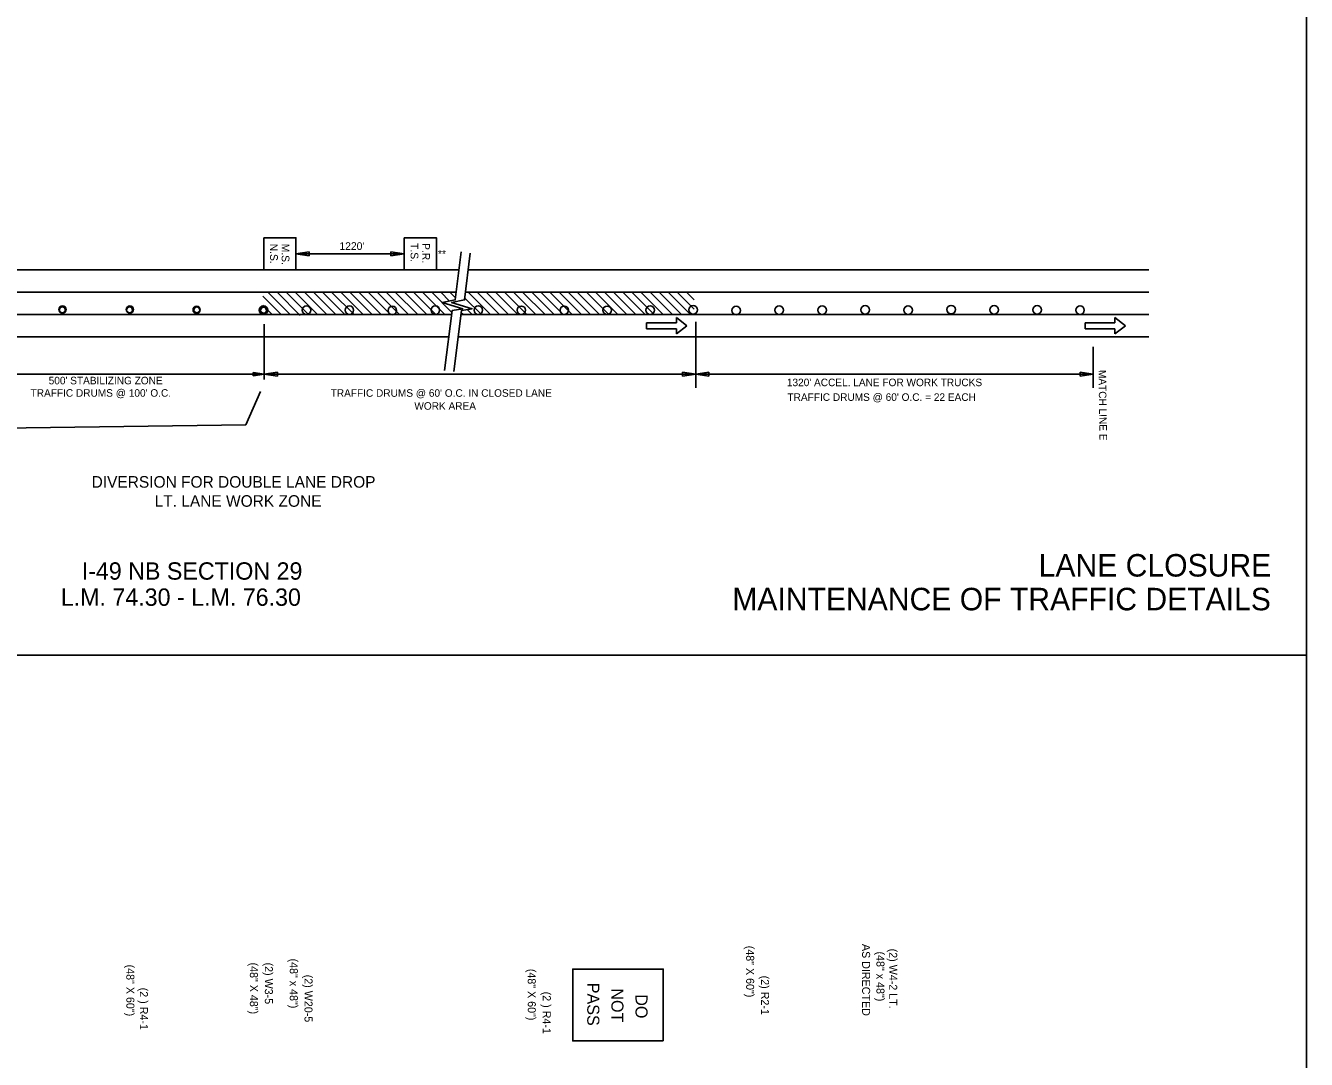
# Model space of a CAD drawing. Extents: x -100 to 745, y -1581 to -107.
# Drawn here: x 245.8 to 345.4, y -732 to -651.6 of the extents above; entities that cross this region are included whole.
import ezdxf

# ---------------------------------------------------------------- set-up
doc = ezdxf.new("R2010")
doc.units = 0
for name, color, linetype in [('Default', 7, 'Continuous'), ('R_Contour Annot', 7, 'Continuous'), ('R_Draft', 7, 'Continuous'), ('R_MOT', 7, 'Continuous'), ('R_ROW', 7, 'Continuous')]:
    doc.layers.add(name, color=color, linetype=linetype)

msp = doc.modelspace()

# ---------------------------------------------------------------- linework, layer by layer
at = {"layer": 'Default'}
for p, q in [((266.853, -669.361), (267.883, -669.206)), ((275.274, -669.361), (266.853, -669.361)), ((267.883, -669.515), (266.853, -669.361)), ((267.883, -669.206), (267.883, -669.515)), ((274.243, -669.515), (274.243, -669.206)), ((274.243, -669.206), (275.274, -669.361)), ((275.274, -669.361), (274.243, -669.515)), ((220.475, -670.611), (279.525, -670.611)), ((280.254, -670.611), (333.152, -670.611)), ((220.692, -672.349), (279.316, -672.349)), ((264.277, -672.648), (265.717, -674.088)), ((264.685, -672.349), (266.424, -674.088)), ((265.393, -672.349), (267.186, -674.143)), ((266.1, -672.349), (267.838, -674.088)), ((266.807, -672.349), (268.545, -674.088)), ((267.514, -672.349), (269.252, -674.088)), ((268.221, -672.349), (269.959, -674.088)), ((268.928, -672.349), (270.666, -674.088)), ((269.635, -672.349), (271.374, -674.088)), ((270.342, -672.349), (272.081, -674.088)), ((271.049, -672.349), (272.788, -674.088)), ((271.757, -672.349), (273.495, -674.088)), ((272.464, -672.349), (274.202, -674.088)), ((273.171, -672.349), (274.909, -674.088)), ((273.878, -672.349), (275.616, -674.088)), ((274.585, -672.349), (276.323, -674.088)), ((275.292, -672.349), (277.03, -674.088)), ((275.999, -672.349), (277.737, -674.088)), ((276.706, -672.349), (278.445, -674.088)), ((277.413, -672.349), (278.983, -673.919)), ((278.121, -672.349), (278.802, -673.03)), ((278.827, -672.349), (279.263, -672.785)), ((279.99, -672.804), (281.273, -674.088)), ((280.044, -672.349), (333.152, -672.349)), ((280.242, -672.349), (281.98, -674.088)), ((280.949, -672.349), (282.687, -674.088)), ((281.656, -672.349), (283.394, -674.088)), ((282.363, -672.349), (284.101, -674.088)), ((283.07, -672.349), (284.809, -674.088)), ((283.777, -672.349), (285.516, -674.088)), ((284.484, -672.349), (286.223, -674.088)), ((285.192, -672.349), (286.93, -674.088)), ((285.899, -672.349), (287.637, -674.088)), ((286.606, -672.349), (288.344, -674.088)), ((287.313, -672.349), (289.051, -674.088)), ((288.02, -672.349), (289.758, -674.088)), ((288.727, -672.349), (290.465, -674.088)), ((289.434, -672.349), (291.172, -674.088)), ((290.141, -672.349), (291.88, -674.088)), ((290.848, -672.349), (292.587, -674.088)), ((291.556, -672.349), (293.294, -674.088)), ((292.263, -672.349), (294.001, -674.088)), ((292.97, -672.349), (294.708, -674.088)), ((293.677, -672.349), (295.415, -674.088)), ((294.384, -672.349), (296.122, -674.088)), ((295.091, -672.349), (296.829, -674.088)), ((295.798, -672.349), (297.536, -674.088)), ((296.505, -672.349), (297.812, -673.656)), ((297.212, -672.349), (297.812, -672.949)), ((264.277, -673.355), (265.01, -674.088)), ((279.709, -673.938), (279.859, -674.088)), ((280.172, -673.694), (280.566, -674.088)), ((221.048, -674.088), (278.962, -674.088)), ((264.398, -679.129), (264.398, -674.824)), ((279.69, -674.088), (333.152, -674.088)), ((296.438, -674.72), (294.113, -674.72)), ((294.113, -675.194), (294.113, -674.72)), ((296.438, -674.72), (296.438, -674.324)), ((297.259, -674.957), (296.438, -674.324)), ((296.438, -675.589), (297.259, -674.957)), ((297.933, -679.793), (297.933, -674.648)), ((330.524, -674.72), (328.198, -674.72)), ((328.198, -675.194), (328.198, -674.72)), ((330.524, -674.72), (330.524, -674.324)), ((331.344, -674.957), (330.524, -674.324)), ((330.524, -675.589), (331.344, -674.957)), ((220.528, -675.826), (278.745, -675.826)), ((279.473, -675.826), (333.152, -675.826)), ((296.438, -675.194), (294.113, -675.194)), ((296.438, -675.589), (296.438, -675.194)), ((330.524, -675.194), (328.198, -675.194)), ((330.524, -675.589), (330.524, -675.194)), ((328.843, -679.793), (328.843, -676.602)), ((264.398, -678.715), (238.32, -678.715)), ((264.398, -678.715), (263.528, -678.584)), ((263.528, -678.584), (263.528, -678.845)), ((263.528, -678.845), (264.398, -678.715)), ((265.428, -678.56), (264.398, -678.715)), ((297.933, -678.715), (264.398, -678.715)), ((264.398, -678.715), (265.428, -678.87)), ((265.428, -678.87), (265.428, -678.56)), ((297.933, -678.715), (296.902, -678.56)), ((296.902, -678.56), (296.902, -678.869)), ((296.902, -678.869), (297.933, -678.715)), ((298.963, -678.56), (297.933, -678.715)), ((328.843, -678.715), (297.933, -678.715)), ((297.933, -678.715), (298.963, -678.87)), ((298.963, -678.87), (298.963, -678.56)), ((328.843, -678.715), (327.813, -678.56)), ((327.813, -678.56), (327.813, -678.87)), ((327.813, -678.87), (328.843, -678.715))]:
    msp.add_line(p, q, dxfattribs=at)
for points in [[(264.353, -668.111), (266.853, -668.111), (266.853, -670.611), (264.353, -670.611)], [(275.274, -668.111), (277.774, -668.111), (277.774, -670.611), (275.274, -670.611)], [(295.412, -730.566), (288.372, -730.566), (288.372, -724.98), (295.412, -724.98)]]:
    msp.add_lwpolyline(points, close=True, dxfattribs=at)
for points in [[(278.42, -678.429), (279.001, -673.772), (279.827, -673.626), (278.224, -673.14), (279.244, -672.946), (279.694, -669.211)], [(279.137, -678.518), (279.73, -673.772), (280.555, -673.626), (278.953, -673.14), (279.973, -672.946), (280.412, -669.297)], [(193.606, -680.302), (195.581, -682.919), (237.407, -682.968), (238.213, -685.387), (238.285, -683.002), (262.954, -682.669), (264.095, -680.071)]]:
    msp.add_lwpolyline(points, dxfattribs=at)
for centre, radius in [((248.712, -673.688), 0.281), ((248.704, -673.718), 0.229), ((253.954, -673.688), 0.281), ((253.931, -673.718), 0.229), ((259.141, -673.715), 0.281), ((259.158, -673.718), 0.229), ((264.332, -673.745), 0.333), ((264.327, -673.741), 0.281), ((264.345, -673.744), 0.229), ((267.673, -673.745), 0.333), ((271.014, -673.746), 0.333), ((274.355, -673.766), 0.333), ((277.696, -673.745), 0.333), ((281.037, -673.734), 0.333), ((284.379, -673.75), 0.333), ((287.72, -673.75), 0.333), ((291.061, -673.75), 0.333), ((294.402, -673.735), 0.333), ((297.743, -673.722), 0.333), ((301.084, -673.77), 0.333), ((304.425, -673.738), 0.333), ((307.766, -673.738), 0.333), ((311.107, -673.722), 0.333), ((314.448, -673.736), 0.333), ((317.789, -673.7), 0.333), ((321.13, -673.722), 0.333), ((324.471, -673.719), 0.333), ((327.812, -673.735), 0.333)]:
    msp.add_circle(centre, radius, dxfattribs=at)
at = {"layer": 'R_Contour Annot'}
for points in [[(175.406, -590.582), (345.406, -590.582), (345.406, -700.582), (175.406, -700.582)], [(175.406, -700.582), (345.406, -700.582), (345.406, -810.582), (175.406, -810.582)]]:
    msp.add_lwpolyline(points, close=True, dxfattribs=at)
at = {"layer": 'R_Draft'}
for points in [[(175.406, -590.582), (175.406, -700.582), (345.406, -700.582), (345.406, -590.582)], [(175.406, -700.582), (175.406, -810.582), (345.406, -810.582), (345.406, -700.582)]]:
    msp.add_lwpolyline(points, close=True, dxfattribs=at)

# ---------------------------------------------------------------- texts
at = {"layer": 'Default'}
for s, height, rotation, p in [('N.S.', 0.6, 270, (264.853, -668.569)), ('M.S.', 0.6, 270, (265.753, -668.569)), ('T.S.', 0.6, 270, (275.774, -668.522)), ('P.R.', 0.6, 270, (276.674, -668.522)), ('MATCH LINE E', 0.5862, 270.80593, (329.249, -678.396)), ('(48" X 60")', 0.6222, 270, (301.857, -723.166)), ('AS DIRECTED ', 0.6222, 270, (310.87, -723.027)), ('(48" x 48")', 0.6222, 270, (311.988, -723.616)), ('(2) W4-2 LT.', 0.6222, 270, (312.975, -723.394)), ('(48" X 60")', 0.6222, 270, (253.679, -724.634)), ('(48" X 48")', 0.6222, 270, (263.28, -724.474)), ('(2) W3-5', 0.6222, 270, (264.443, -724.474)), ('(48" x 48")', 0.6222, 270, (266.385, -724.163)), ('(2) W20-5', 0.6222, 270, (267.527, -725.42)), ('(48" X 60")', 0.6222, 270, (284.882, -724.962)), ('(2) R2-1', 0.6222, 270, (303.015, -725.492)), ('(2 ) R4-1', 0.6222, 270, (254.731, -726.43)), ('PASS', 0.937, 270, (289.507, -726.045)), ('NOT', 0.9371, 270, (291.381, -726.481)), ('(2 ) R4-1', 0.6222, 270, (286.051, -726.739)), ('DO', 0.9371, 270, (293.255, -726.939))]:
    msp.add_text(s, height=height, rotation=rotation, dxfattribs=at).set_placement(p)
for s, height, p in [("1220'", 0.6, (270.241, -669.057)), ('**', 0.6, (277.897, -669.661)), ("500' STABILIZING ZONE", 0.5862, (247.639, -679.507)), ("TRAFFIC DRUMS @ 100' O.C.", 0.5862, (246.234, -680.471)), ("TRAFFIC DRUMS @ 60' O.C. IN CLOSED LANE", 0.5862, (269.561, -680.476)), ("1320' ACCEL. LANE FOR WORK TRUCKS", 0.5862, (305.022, -679.652)), ('WORK AREA', 0.5862, (276.065, -681.484)), ("TRAFFIC DRUMS @ 60' O.C. = 22 EACH", 0.5862, (305.07, -680.795)), ('I-49 NB SECTION 29', 1.35, (250.207, -694.699)), ('L.M. 74.30 - L.M. 76.30', 1.35, (248.58, -696.732))]:
    msp.add_text(s, height=height, dxfattribs=at).set_placement(p)
at = {"layer": 'R_MOT'}
for s, p in [('LANE CLOSURE', (324.596, -694.457)), ('MAINTENANCE OF TRAFFIC DETAILS', (300.779, -697.082))]:
    msp.add_text(s, height=1.75, dxfattribs=at).set_placement(p)
at = {"layer": 'R_ROW'}
for s, p in [('DIVERSION FOR DOUBLE LANE DROP', (250.976, -687.545)), ('LT. LANE WORK ZONE', (255.876, -689.03))]:
    msp.add_text(s, height=0.9, dxfattribs=at).set_placement(p)

doc.saveas('drawing.dxf')
